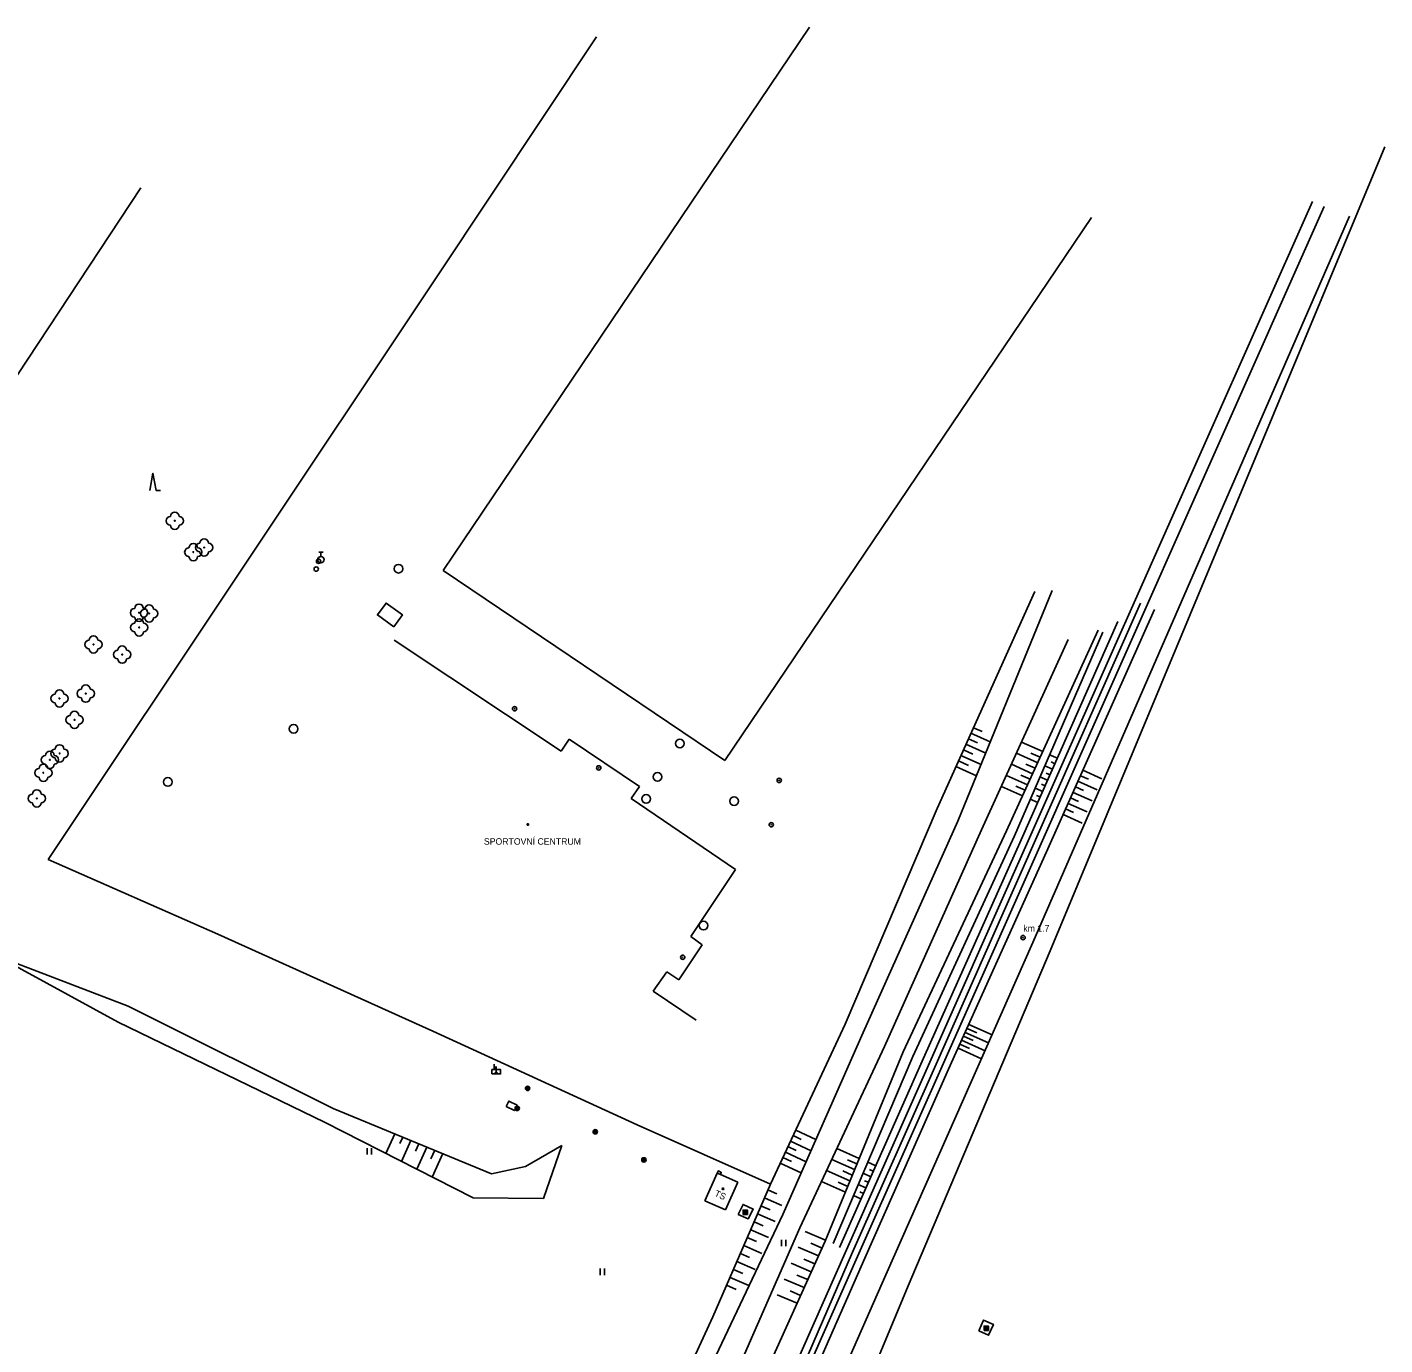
# Model space of a CAD drawing. Extents: x -539694 to -539148, y -1156467 to -1155920.
# Drawn here: x -539304.5 to -539147.8, y -1156123.3 to -1155971.2 of the extents above; entities that cross this region are included whole.
import ezdxf

# ---------------------------------------------------------------- set-up
doc = ezdxf.new("R2010")
doc.units = 0
for name, color, linetype in [('Vrstva 11', 7, 'Continuous'), ('Vrstva 12', 7, 'Continuous'), ('Vrstva 13', 7, 'Continuous'), ('Vrstva 14', 7, 'Continuous'), ('Vrstva 15', 7, 'Continuous'), ('Vrstva 22', 7, 'Continuous'), ('Vrstva 23', 7, 'Continuous'), ('Vrstva 24', 7, 'Continuous'), ('Vrstva 25', 7, 'Continuous'), ('Vrstva 27', 7, 'Continuous'), ('Vrstva 28', 7, 'Continuous'), ('Vrstva 36', 7, 'Continuous'), ('Vrstva 39', 7, 'Continuous'), ('Vrstva 41', 7, 'Continuous'), ('Vrstva 5', 7, 'Continuous'), ('Vrstva 7', 7, 'Continuous')]:
    doc.layers.add(name, color=color, linetype=linetype)

msp = doc.modelspace()

# ---------------------------------------------------------------- linework, layer by layer
at = {"layer": 'Vrstva 11'}
for points in [[(-539262.16, -1156040.44), (-539261.17, -1156039.07), (-539263.06, -1156037.72), (-539264.05, -1156039.07), (-539262.16, -1156040.44)], [(-539222.42, -1156108.27), (-539221.27, -1156108.79), (-539220.67, -1156107.66), (-539221.84, -1156107.12), (-539222.42, -1156108.27)], [(-539194.65, -1156121.71), (-539193.509, -1156122.225), (-539192.96, -1156120.96), (-539194.09, -1156120.47), (-539194.65, -1156121.71)]]:
    msp.add_lwpolyline(points, dxfattribs=at)
at = {"layer": 'Vrstva 12'}
for p, q in [((-539156.12, -1155991.37), (-539193.29, -1156074.94)), ((-539191.89, -1156075.52), (-539154.76, -1155991.95)), ((-539193.29, -1156074.94), (-539209.89, -1156112.37)), ((-539208.62, -1156113.13), (-539191.89, -1156075.52)), ((-539209.89, -1156112.37), (-539249.61, -1156201.56)), ((-539227.275, -1156155.059), (-539208.62, -1156113.13))]:
    msp.add_line(p, q, dxfattribs=at)
for radius in [0.25, 0.03]:
    msp.add_circle((-539189.53, -1156076.32), radius, dxfattribs=at)
at = {"layer": 'Vrstva 13'}
for p, q in [((-539188.4, -1156065.74), (-539175.99, -1156037.74)), ((-539199.56, -1156090.92), (-539188.4, -1156065.74)), ((-539209.23, -1156112.62), (-539199.56, -1156090.92)), ((-539214.92, -1156125.78), (-539209.23, -1156112.62))]:
    msp.add_line(p, q, dxfattribs=at)
at = {"layer": 'Vrstva 14'}
for p, q in [((-539151.84, -1155993.07), (-539188.4, -1156076.89)), ((-539197.04, -1156062.87), (-539186.16, -1156036.26)), ((-539186.83, -1156066.43), (-539174.35, -1156038.45)), ((-539189.73, -1156065.02), (-539178.58, -1156039.82)), ((-539194.32, -1156063.9), (-539184.33, -1156041.91)), ((-539180.85, -1156040.84), (-539191.44, -1156064.01)), ((-539190.53, -1156064.58), (-539180.33, -1156041.06)), ((-539207.98, -1156087.28), (-539197.04, -1156062.87)), ((-539205.53, -1156088.89), (-539194.32, -1156063.9)), ((-539191.44, -1156064.01), (-539203.37, -1156089.5)), ((-539202.26, -1156090.04), (-539190.53, -1156064.58)), ((-539201.02, -1156090.24), (-539189.73, -1156065.02)), ((-539198.12, -1156091.51), (-539186.83, -1156066.43)), ((-539188.4, -1156076.89), (-539205.35, -1156115.23)), ((-539292.84, -1156084.22), (-539308.06, -1156078.41)), ((-539308.06, -1156078.41), (-539293.98, -1156086.09)), ((-539269.14, -1156096.06), (-539292.84, -1156084.22)), ((-539293.98, -1156086.09), (-539270.17, -1156097.62)), ((-539217.24, -1156108.26), (-539207.98, -1156087.28)), ((-539215.28, -1156109.8), (-539205.53, -1156088.89)), ((-539203.37, -1156089.5), (-539212.37, -1156111.34)), ((-539211.44, -1156111.61), (-539202.26, -1156090.04)), ((-539210.72, -1156112.07), (-539201.02, -1156090.24)), ((-539207.8, -1156113.31), (-539198.12, -1156091.51)), ((-539250.87, -1156103.57), (-539269.14, -1156096.06)), ((-539270.17, -1156097.62), (-539252.99, -1156106.37)), ((-539244.9, -1156106.42), (-539242.78, -1156100.33)), ((-539225.33, -1156120.1), (-539218.68, -1156104.76)), ((-539252.99, -1156106.37), (-539244.9, -1156106.42)), ((-539233.91, -1156143.39), (-539217.24, -1156108.26)), ((-539230.39, -1156144.21), (-539215.28, -1156109.8)), ((-539218.48, -1156124.89), (-539212.37, -1156111.34)), ((-539205.35, -1156115.23), (-539223.699, -1156156.669)), ((-539235.13, -1156141.3), (-539225.33, -1156120.1))]:
    msp.add_line(p, q, dxfattribs=at)
for points in [[(-539242.78, -1156100.33), (-539246.97, -1156102.72), (-539250.87, -1156103.57)], [(-539301.35, -1156326.15), (-539226.818, -1156156.579), (-539226.336, -1156155.482), (-539207.8, -1156113.31)]]:
    msp.add_lwpolyline(points, dxfattribs=at)
at = {"layer": 'Vrstva 15'}
for p, q in [((-539193.309, -1156053.744), (-539195.546, -1156052.734)), ((-539194.248, -1156052.552), (-539195.259, -1156052.096)), ((-539195.309, -1156055.145), (-539196.41, -1156054.649)), ((-539193.839, -1156055.041), (-539196.122, -1156054.011)), ((-539194.779, -1156053.849), (-539195.834, -1156053.373)), ((-539187.258, -1156054.86), (-539189.718, -1156053.771)), ((-539195.839, -1156056.442), (-539196.986, -1156055.925)), ((-539194.369, -1156056.337), (-539196.698, -1156055.287)), ((-539188.422, -1156057.406), (-539190.877, -1156056.32)), ((-539187.84, -1156056.133), (-539190.297, -1156055.046)), ((-539188.131, -1156056.77), (-539189.212, -1156056.291)), ((-539187.549, -1156055.496), (-539188.633, -1156055.017)), ((-539185.566, -1156055.608), (-539186.466, -1156055.21)), ((-539185.849, -1156056.248), (-539186.296, -1156056.051)), ((-539194.899, -1156057.634), (-539197.273, -1156056.563)), ((-539189.004, -1156058.68), (-539191.456, -1156057.595)), ((-539188.713, -1156058.043), (-539189.791, -1156057.566)), ((-539186.699, -1156058.169), (-539187.58, -1156057.779)), ((-539186.132, -1156056.889), (-539187.023, -1156056.494)), ((-539186.415, -1156057.529), (-539186.853, -1156057.335)), ((-539181.991, -1156058.046), (-539182.908, -1156057.637)), ((-539180.423, -1156057.979), (-539182.623, -1156056.998)), ((-539189.586, -1156059.953), (-539192.035, -1156058.87)), ((-539189.295, -1156059.317), (-539190.37, -1156058.841)), ((-539187.265, -1156059.449), (-539188.137, -1156059.063)), ((-539186.982, -1156058.809), (-539187.41, -1156058.62)), ((-539182.562, -1156059.325), (-539183.478, -1156058.916)), ((-539180.993, -1156059.258), (-539183.193, -1156058.277)), ((-539187.832, -1156060.729), (-539188.695, -1156060.348)), ((-539187.548, -1156060.089), (-539187.967, -1156059.904)), ((-539182.133, -1156061.815), (-539184.333, -1156060.834)), ((-539183.132, -1156060.603), (-539184.048, -1156060.195)), ((-539181.563, -1156060.536), (-539183.763, -1156059.555)), ((-539182.704, -1156063.094), (-539184.904, -1156062.113)), ((-539183.702, -1156061.881), (-539184.618, -1156061.473)), ((-539196.41, -1156087.712), (-539195.294, -1156088.214)), ((-539196.205, -1156087.257), (-539193.518, -1156088.467)), ((-539196, -1156086.8), (-539194.883, -1156087.303)), ((-539195.795, -1156086.345), (-539193.114, -1156087.552)), ((-539197.026, -1156089.081), (-539194.327, -1156090.296)), ((-539196.821, -1156088.624), (-539195.704, -1156089.126)), ((-539196.616, -1156088.169), (-539193.922, -1156089.381)), ((-539213.435, -1156099.638), (-539215.773, -1156098.545)), ((-539262.06, -1156098.97), (-539263.067, -1156101.238)), ((-539261.135, -1156099.351), (-539261.465, -1156100.094)), ((-539260.209, -1156099.731), (-539261.282, -1156102.147)), ((-539259.284, -1156100.111), (-539259.671, -1156100.982)), ((-539214, -1156100.919), (-539216.366, -1156099.813)), ((-539215.135, -1156099.615), (-539216.069, -1156099.179)), ((-539258.359, -1156100.491), (-539259.498, -1156103.056)), ((-539257.434, -1156100.872), (-539257.878, -1156101.87)), ((-539256.509, -1156101.252), (-539257.714, -1156103.964)), ((-539216.266, -1156102.178), (-539217.255, -1156101.715)), ((-539214.565, -1156102.2), (-539216.959, -1156101.081)), ((-539215.701, -1156100.896), (-539216.662, -1156100.447)), ((-539208.439, -1156101.8), (-539211.016, -1156100.655)), ((-539215.131, -1156103.481), (-539217.552, -1156102.349)), ((-539209.506, -1156104.39), (-539212.199, -1156103.193)), ((-539208.972, -1156103.095), (-539211.607, -1156101.924)), ((-539209.239, -1156103.742), (-539210.329, -1156103.258)), ((-539208.705, -1156102.447), (-539209.795, -1156101.963)), ((-539206.532, -1156102.647), (-539207.452, -1156102.238)), ((-539206.817, -1156103.287), (-539207.246, -1156103.096)), ((-539210.039, -1156105.684), (-539212.791, -1156104.462)), ((-539209.773, -1156105.037), (-539210.862, -1156104.553)), ((-539207.669, -1156105.206), (-539208.548, -1156104.815)), ((-539207.101, -1156103.926), (-539208, -1156103.527)), ((-539207.385, -1156104.566), (-539207.815, -1156104.375)), ((-539219.311, -1156106.387), (-539217.371, -1156107.238)), ((-539218.909, -1156105.471), (-539217.948, -1156105.892)), ((-539209.096, -1156106.104), (-539208.238, -1156106.485)), ((-539207.954, -1156105.845), (-539208.383, -1156105.654)), ((-539219.713, -1156107.302), (-539218.733, -1156107.732)), ((-539220.567, -1156109.112), (-539219.518, -1156109.572)), ((-539220.169, -1156108.194), (-539218.137, -1156109.086)), ((-539221.362, -1156110.947), (-539220.302, -1156111.412)), ((-539220.964, -1156110.03), (-539218.902, -1156110.934)), ((-539212.323, -1156111.236), (-539214.688, -1156110.228)), ((-539222.158, -1156112.782), (-539221.087, -1156113.251)), ((-539221.76, -1156111.864), (-539219.668, -1156112.782)), ((-539213.146, -1156113.061), (-539215.49, -1156112.06)), ((-539212.735, -1156112.149), (-539214.042, -1156111.59)), ((-539222.555, -1156113.7), (-539220.434, -1156114.63)), ((-539213.968, -1156114.884), (-539216.292, -1156113.892)), ((-539213.557, -1156113.973), (-539214.836, -1156113.426)), ((-539223.351, -1156115.534), (-539221.2, -1156116.478)), ((-539222.953, -1156114.617), (-539221.872, -1156115.091)), ((-539214.791, -1156116.708), (-539217.094, -1156115.724)), ((-539214.379, -1156115.796), (-539215.63, -1156115.262)), ((-539223.749, -1156116.452), (-539222.656, -1156116.931)), ((-539215.201, -1156117.619), (-539216.423, -1156117.098)), ((-539215.613, -1156118.531), (-539217.896, -1156117.556))]:
    msp.add_line(p, q, dxfattribs=at)
at = {"layer": 'Vrstva 22'}
for centre in [(-539287.45, -1156028.21), (-539284.05, -1156031.3), (-539285.3, -1156031.83), (-539291.57, -1156038.82), (-539290.4, -1156038.91), (-539291.54, -1156040.52), (-539296.82, -1156042.48), (-539293.51, -1156043.66), (-539297.72, -1156048.16), (-539300.75, -1156048.72), (-539299.01, -1156051.19), (-539301.85, -1156055.8), (-539300.73, -1156055.06), (-539302.61, -1156057.3), (-539303.36, -1156060.25)]:
    msp.add_circle(centre, 0.05, dxfattribs=at)
for centre, start, end in [((-539287.95, -1156028.21), 90, 270), ((-539287.45, -1156027.71), 0, 180), ((-539286.95, -1156028.21), 270, 90), ((-539287.45, -1156028.71), 180, 0), ((-539285.3, -1156031.33), 0, 180), ((-539284.55, -1156031.3), 90, 270), ((-539284.05, -1156030.8), 0, 180), ((-539283.55, -1156031.3), 270, 90), ((-539285.8, -1156031.83), 90, 270), ((-539285.3, -1156032.33), 180, 0), ((-539284.8, -1156031.83), 270, 90), ((-539284.05, -1156031.8), 180, 0), ((-539292.07, -1156038.82), 90, 270), ((-539291.57, -1156038.32), 0, 180), ((-539290.9, -1156038.91), 90, 270), ((-539291.07, -1156038.82), 270, 90), ((-539290.4, -1156038.41), 0, 180), ((-539289.9, -1156038.91), 270, 90), ((-539292.04, -1156040.52), 90, 270), ((-539291.57, -1156039.32), 180, 0), ((-539291.54, -1156040.02), 0, 180), ((-539291.04, -1156040.52), 270, 90), ((-539290.4, -1156039.41), 180, 0), ((-539297.32, -1156042.48), 90, 270), ((-539296.82, -1156041.98), 0, 180), ((-539296.32, -1156042.48), 270, 90), ((-539291.54, -1156041.02), 180, 0), ((-539296.82, -1156042.98), 180, 0), ((-539294.01, -1156043.66), 90, 270), ((-539293.51, -1156043.16), 0, 180), ((-539293.01, -1156043.66), 270, 90), ((-539293.51, -1156044.16), 180, 0), ((-539301.25, -1156048.72), 90, 270), ((-539300.75, -1156048.22), 0, 180), ((-539300.25, -1156048.72), 270, 90), ((-539298.22, -1156048.16), 90, 270), ((-539297.72, -1156047.66), 0, 180), ((-539297.22, -1156048.16), 270, 90), ((-539300.75, -1156049.22), 180, 0), ((-539297.72, -1156048.66), 180, 0), ((-539299.51, -1156051.19), 90, 270), ((-539299.01, -1156050.69), 0, 180), ((-539299.01, -1156051.69), 180, 0), ((-539298.51, -1156051.19), 270, 90), ((-539301.85, -1156055.3), 0, 180), ((-539301.23, -1156055.06), 90, 270), ((-539300.73, -1156054.56), 0, 180), ((-539300.23, -1156055.06), 270, 90), ((-539302.61, -1156056.8), 0, 180), ((-539302.35, -1156055.8), 90, 270), ((-539301.85, -1156056.3), 180, 0), ((-539301.35, -1156055.8), 270, 90), ((-539300.73, -1156055.56), 180, 0), ((-539303.11, -1156057.3), 90, 270), ((-539302.61, -1156057.8), 180, 0), ((-539302.11, -1156057.3), 270, 90), ((-539303.36, -1156059.75), 0, 180), ((-539303.86, -1156060.25), 90, 270), ((-539303.36, -1156060.75), 180, 0), ((-539302.86, -1156060.25), 270, 90)]:
    msp.add_arc(centre, 0.5, start, end, dxfattribs=at)
at = {"layer": 'Vrstva 23'}
for p, q in [((-539147.771, -1155985.067), (-539186.39, -1156077.83)), ((-539186.39, -1156077.83), (-539202.8, -1156116.53)), ((-539202.8, -1156116.53), (-539215.34, -1156146.71))]:
    msp.add_line(p, q, dxfattribs=at)
at = {"layer": 'Vrstva 24'}
for p, q in [((-539250.59, -1156090.934), (-539250.59, -1156091.561)), ((-539250.59, -1156091.561), (-539250.34, -1156091.185)), ((-539250.449, -1156091.815), (-539250.34, -1156092.06)), ((-539250.34, -1156091.185), (-539250.34, -1156092.06)), ((-539250.34, -1156092.06), (-539250.229, -1156091.815))]:
    msp.add_line(p, q, dxfattribs=at)
msp.add_lwpolyline([(-539250.84, -1156092.06), (-539249.84, -1156092.06), (-539249.84, -1156091.56), (-539250.84, -1156091.56)], close=True, dxfattribs=at)
for points in [[(-539249.193, -1156095.827), (-539248.24, -1156096.28), (-539247.937, -1156095.643), (-539248.89, -1156095.19), (-539249.193, -1156095.827)], [(-539224.464, -1156103.653), (-539224.36, -1156103.42), (-539224.69, -1156103.24), (-539224.83, -1156103.49)]]:
    msp.add_lwpolyline(points, dxfattribs=at)
at = {"layer": 'Vrstva 25'}
for points in [[(-539221.85, -1156108.27), (-539221.35, -1156108.27), (-539221.35, -1156107.77), (-539221.85, -1156107.77)], [(-539221.8, -1156108.22), (-539221.4, -1156108.22), (-539221.4, -1156107.82), (-539221.8, -1156107.82)], [(-539221.75, -1156108.17), (-539221.45, -1156108.17), (-539221.45, -1156107.87), (-539221.75, -1156107.87)], [(-539221.7, -1156108.12), (-539221.5, -1156108.12), (-539221.5, -1156107.92), (-539221.7, -1156107.92)], [(-539221.65, -1156108.069), (-539221.551, -1156108.07), (-539221.55, -1156107.971), (-539221.649, -1156107.97)], [(-539194.03, -1156121.65), (-539193.53, -1156121.65), (-539193.53, -1156121.15), (-539194.03, -1156121.15)], [(-539193.98, -1156121.6), (-539193.58, -1156121.6), (-539193.58, -1156121.2), (-539193.98, -1156121.2)], [(-539193.93, -1156121.55), (-539193.63, -1156121.55), (-539193.63, -1156121.25), (-539193.93, -1156121.25)], [(-539193.88, -1156121.5), (-539193.68, -1156121.5), (-539193.68, -1156121.3), (-539193.88, -1156121.3)], [(-539193.83, -1156121.45), (-539193.73, -1156121.45), (-539193.73, -1156121.35), (-539193.83, -1156121.35)]]:
    msp.add_lwpolyline(points, close=True, dxfattribs=at)
for centre, radius in [((-539248.22, -1156049.91), 0.25), ((-539248.22, -1156049.91), 0.0303), ((-539238.5, -1156056.73), 0.25), ((-539238.5, -1156056.73), 0.0303), ((-539217.68, -1156058.18), 0.25), ((-539217.68, -1156058.18), 0.0303), ((-539218.6, -1156063.29), 0.25), ((-539218.6, -1156063.29), 0.0303), ((-539228.81, -1156078.59), 0.25), ((-539228.81, -1156078.59), 0.0303), ((-539246.72, -1156093.72), 0.25), ((-539246.72, -1156093.72), 0.2), ((-539246.72, -1156093.72), 0.15), ((-539246.72, -1156093.72), 0.1), ((-539246.72, -1156093.72), 0.05), ((-539247.92, -1156096.03), 0.25), ((-539247.92, -1156096.03), 0.2), ((-539247.92, -1156096.03), 0.15), ((-539247.92, -1156096.03), 0.1), ((-539247.92, -1156096.03), 0.05), ((-539238.903, -1156098.735), 0.25), ((-539238.903, -1156098.735), 0.2), ((-539238.903, -1156098.735), 0.15), ((-539238.903, -1156098.735), 0.1), ((-539238.903, -1156098.735), 0.05), ((-539233.3, -1156101.97), 0.25), ((-539233.3, -1156101.97), 0.2), ((-539233.3, -1156101.97), 0.15), ((-539233.3, -1156101.97), 0.1), ((-539233.3, -1156101.97), 0.05)]:
    msp.add_circle(centre, radius, dxfattribs=at)
at = {"layer": 'Vrstva 27'}
for centre in [(-539261.61, -1156033.74), (-539273.72, -1156052.22), (-539229.14, -1156053.92), (-539288.24, -1156058.36), (-539231.72, -1156057.77), (-539233.04, -1156060.32), (-539222.89, -1156060.57), (-539226.41, -1156074.94)]:
    msp.add_circle(centre, 0.5, dxfattribs=at)
at = {"layer": 'Vrstva 28'}
for p, q in [((-539270.82, -1156031.825), (-539270.32, -1156031.825)), ((-539270.57, -1156032.325), (-539270.57, -1156031.825))]:
    msp.add_line(p, q, dxfattribs=at)
for centre, radius in [((-539270.85, -1156032.88), 0.25), ((-539270.57, -1156032.7), 0.375), ((-539271.12, -1156033.79), 0.25)]:
    msp.add_circle(centre, radius, dxfattribs=at)
at = {"layer": 'Vrstva 36'}
for p, q in [((-539265.248, -1156101.362), (-539265.248, -1156100.612)), ((-539264.748, -1156101.362), (-539264.748, -1156100.612)), ((-539217.4, -1156111.935), (-539217.4, -1156111.185)), ((-539216.9, -1156111.935), (-539216.9, -1156111.185)), ((-539238.331, -1156115.277), (-539238.331, -1156114.527)), ((-539237.831, -1156115.277), (-539237.831, -1156114.527))]:
    msp.add_line(p, q, dxfattribs=at)
msp.add_lwpolyline([(-539290.338, -1156024.721), (-539289.963, -1156022.721), (-539289.588, -1156024.721), (-539289.088, -1156024.721)], dxfattribs=at)
at = {"layer": 'Vrstva 39'}
for centre, radius in [((-539246.69, -1156063.27), 0.09), ((-539246.69, -1156063.27), 0.0398), ((-539224.16, -1156105.314), 0.09), ((-539224.16, -1156105.314), 0.0398)]:
    msp.add_circle(centre, radius, dxfattribs=at)
at = {"layer": 'Vrstva 5'}
for p, q in [((-539256.48, -1156033.94), (-539214.18, -1155971.24)), ((-539291.363, -1155989.785), (-539314.48, -1156024.79)), ((-539181.62, -1155993.19), (-539223.97, -1156055.89)), ((-539223.97, -1156055.89), (-539256.48, -1156033.94)), ((-539262.13, -1156042), (-539242.85, -1156054.81)), ((-539242.85, -1156054.81), (-539241.91, -1156053.41)), ((-539241.91, -1156053.41), (-539233.81, -1156058.88)), ((-539233.81, -1156058.88), (-539234.75, -1156060.28)), ((-539234.75, -1156060.28), (-539222.73, -1156068.46)), ((-539222.73, -1156068.46), (-539227.87, -1156076.2)), ((-539227.87, -1156076.2), (-539226.55, -1156077.14)), ((-539226.55, -1156077.14), (-539229.27, -1156081.18)), ((-539230.66, -1156080.26), (-539232.21, -1156082.49)), ((-539229.27, -1156081.18), (-539230.66, -1156080.26)), ((-539232.21, -1156082.49), (-539227.27, -1156085.84)), ((-539226.25, -1156106.69), (-539224.83, -1156103.49)), ((-539222.45, -1156104.55), (-539223.88, -1156107.75)), ((-539223.88, -1156107.75), (-539226.25, -1156106.69))]:
    msp.add_line(p, q, dxfattribs=at)
msp.add_lwpolyline([(-539224.83, -1156103.49), (-539224.464, -1156103.653), (-539222.45, -1156104.55)], dxfattribs=at)
at = {"layer": 'Vrstva 7'}
for p, q in [((-539188.16, -1156036.36), (-539199.46, -1156061.41)), ((-539199.46, -1156061.41), (-539210.05, -1156086.31)), ((-539282.47, -1156075.93), (-539302.05, -1156067.3)), ((-539257.66, -1156087.12), (-539282.47, -1156075.93)), ((-539234.08, -1156097.92), (-539257.66, -1156087.12)), ((-539210.05, -1156086.31), (-539218.68, -1156104.76)), ((-539218.68, -1156104.76), (-539234.08, -1156097.92))]:
    msp.add_line(p, q, dxfattribs=at)
msp.add_lwpolyline([(-539302.05, -1156067.3), (-539257.12, -1155999.93), (-539238.76, -1155972.37)], dxfattribs=at)

# ---------------------------------------------------------------- texts
at = {"layer": 'Vrstva 41'}
for s, p in [('SPORTOVNÍ CENTRUM', (-539251.76, -1156065.6)), ('km 1.7', (-539189.5, -1156075.628))]:
    msp.add_text(s, height=0.75, dxfattribs=at).set_placement(p)
msp.add_text('TS', height=0.75, rotation=335.90307, dxfattribs=at).set_placement((-539225.212, -1156106.114))

doc.saveas('drawing.dxf')
